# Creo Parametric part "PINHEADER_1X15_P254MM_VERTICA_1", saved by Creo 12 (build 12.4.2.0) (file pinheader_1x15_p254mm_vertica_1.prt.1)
Units: Custom; MM, KILOGRAM, SECS

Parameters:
  PTC_WM_ITERATION = "0"
  PTC_WM_VERSION = "-.0"
  PTC_WM_LIFECYCLE_STATE = "In Work"
  PTC_WM_LIFECYCLE = "MO_CADDocument"
  PTC_WM_CREATED_BY = "Maximilian Roepper (Z0017RMS: MO)"
  PTC_WM_CREATED_ON = "18-Sep-26 11:36:42 AM"
  PTC_WM_MODIFIED_BY = "Maximilian Roepper (Z0017RMS: MO)"
  PTC_WM_MODIFIED_ON = "18-Sep-26 11:36:46 AM"
  PDMLINKNUMBER = "PDM000071455159"
  PTC_WM_NAME = "pinheader_1x15_p254mm_vertica_1.prt"
  PTC_WM_NUMBER = "PDM000071455159"

Other parameters: WEIGHT, WEIGHT_FACTOR, WEIGHT_ADD, _MASS_TEMP, _DIFF_TEMP, MC_ERRORS, SUPPLIER

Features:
  1. coordinate system
  2. datum plane "PRT_YZ"
  3. datum plane "PRT_XY"
  4. datum plane "PRT_XZ"
  5. coordinate system
  6. datum axis
  7. datum axis
  8. datum axis
  9. coordinate system
  10. imported feature

Other named items: PRT, SIEMENS_MO, DRW_VIEW_ORG, PRT_X, PRT_Y, PRT_Z, CS0, ROUGH_GROB

Layers: 00_STD_CSYS-KSYS, 01_STD_PLANES-EBENEN, 02_STD_AXES-ACHSEN, 03_STD_CSYS-KSYS, 24_IMPORT_FEAT-IMPORT_KE

Surfaces: 364 plane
